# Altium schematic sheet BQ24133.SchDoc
size A4
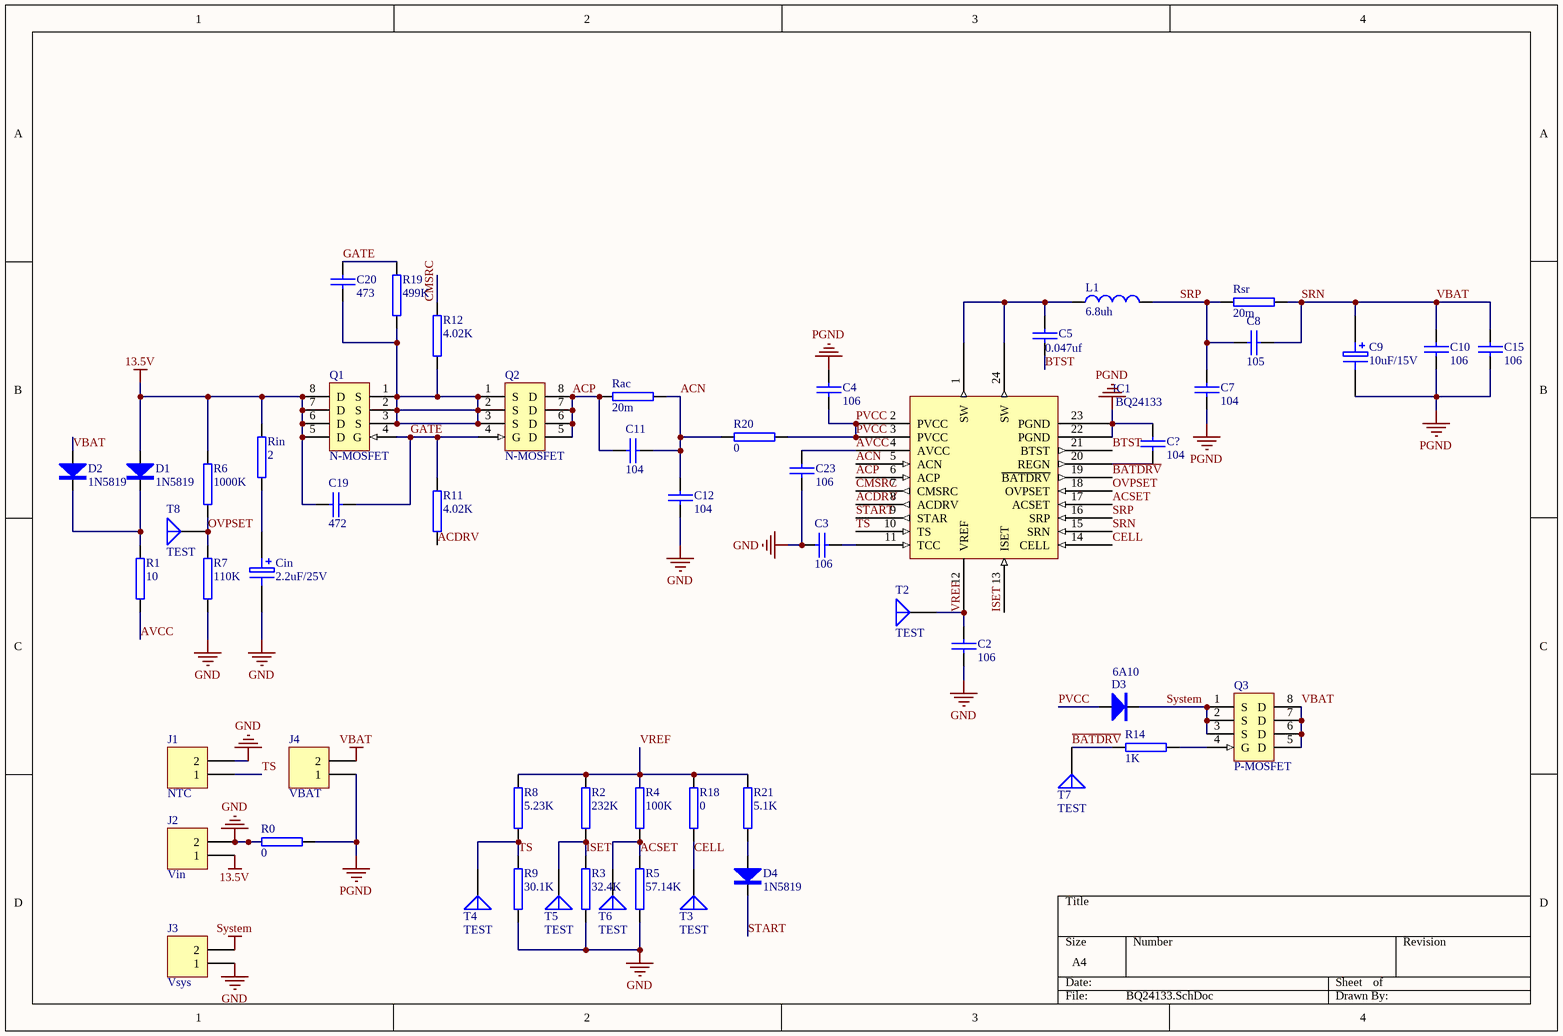
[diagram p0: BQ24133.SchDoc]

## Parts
C2  106  [C0603]
C3  106  [C0603]
C4  106  [C0603]
C5  0.047uf  [C0603]
C7  104  [C0603]
C8  105  [C0603]
C9  10uF/15V  [RB.10]
C10  106  [C1206]
C11  104  [C0603]
C12  104  [C0603]
C15  106  [C1206]
C19  472  [C0603]
C20  473  [C0603]
C23  106  [C0603]
C?  104  [C0603]
Cin  2.2uF/25V  [RB.10]
D1  1N5819  [SOD-323]
D2  1N5819  [SOD-323]
D3  6A10  [6A10]
D4  1N5819  [SOD-323]
IC1  BQ24133  [LC-VQFN-24_3.5x5.5x05P]
J1  NTC  [PH2]
J2  Vin  [VH3.96-2A]
J3  Vsys  [VH3.96-2A]
J4  VBAT  [VH3.96-2A]
L1  6.8uh  [SWPA5040S6R8]
Q1  N-MOSFET  [SOIC-8]
Q2  N-MOSFET  [SOIC-8]
Q3  P-MOSFET  [SOIC-8]
R0  0  [0805]
R1  10  [0603]
R2  232K  [0603]
R3  32.4K  [0603]
R4  100K  [0603]
R5  57.14K  [0603]
R6  1000K  [0603]
R7  110K  [0603]
R8  5.23K  [0603]
R9  30.1K  [0603]
R11  4.02K  [0603]
R12  4.02K  [0603]
R14  1K  [0603]
R18  0  [0603]
R19  499K  [0603]
R20  0  [3216[1206]]
R21  5.1K  [0603]
Rac  20m  [3225[1210]]
Rin  2  [0603]
Rsr  20m  [3225[1210]]
T2  TEST  [SIP-1]
T3  TEST  [SIP-1]
T4  TEST  [SIP-1]
T5  TEST  [SIP-1]
T6  TEST  [SIP-1]
T7  TEST  [SIP-1]
T8  TEST  [SIP-1]

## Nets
13.5V: C19.1 D1.1 J2.1 Q1.5(D) Q1.6(D) Q1.7(D) Q1.8(D) R6.1 Rin.1
GND: C2.2 C3.1 C12.2 C23.2 Cin.2 J1.2 J2.2 J3.1 R0.2 R3.1 R5.2 R7.2 R9.2
PGND: C4.1 C7.2 C9.2 C10.2 C15.1 C?.1 IC1.22(PGND) IC1.23(PGND) J4.1 R0.1
SRN: C8.2 C9.1 C10.1 C15.2 D2.1 IC1.15(SRN) J4.2 Q3.5(D) Q3.6(D) Q3.7(D) Q3.8(D) Rsr.1  [also labelled VBAT]
System: D3.2 J3.2 Q3.1(S) Q3.2(S) Q3.3(S)
ACDRV: IC1.8(ACDRV) R11.2
ACN: C11.2 C12.1 IC1.5(ACN) R20.2 Rac.1
ACP: C11.1 IC1.6(ACP) Q2.5(D) Q2.6(D) Q2.7(D) Q2.8(D) Rac.2
ACSET: IC1.17(ACSET) R4.2 R5.1 T6.1(A)
AVCC: C23.1 IC1.4(AVCC) R1.2
~{BATDRV}: IC1.19(~{BATDRV}) R14.2 T7.1(A)
BTST: C5.2 IC1.21(BTST)
CELL: IC1.14(CELL) R18.2 T3.1(A)
CMSRC: IC1.7(CMSRC) R12.1
GATE: C19.2 C20.1 Q1.4(G) Q2.4(G) R11.1 R19.1
ISET: IC1.13(ISET) R2.1 R3.2 T5.1(A)
OVPSET: IC1.18(OVPSET) R6.2 R7.1 T8.1(A)
PVCC: C4.2 D3.1 IC1.2(PVCC) IC1.3(PVCC) R20.1
SRP: C7.1 C8.1 IC1.16(SRP) L1.2 Rsr.2
START: D4.2 IC1.9(STAR)
TS: IC1.10(TS) J1.1 R8.2 R9.1 T4.1(A)
VREF: C2.1 IC1.12(VREF) R2.2 R4.1 R8.1 R18.1 R21.1 T2.1(A)
NetC3_2: C3.2 IC1.11(TCC)
NetC5_1: C5.1 IC1.1(SW) IC1.24(SW) L1.1
NetC20_2: C20.2 Q1.1(S) Q1.2(S) Q1.3(S) Q2.1(S) Q2.2(S) Q2.3(S) R12.2 R19.2
NetC?_2: C?.2 IC1.20(REGN)
NetCin_1: Cin.1 Rin.2
NetD1_2: D1.2 D2.2 R1.1
NetD4_1: D4.1 R21.2
NetQ3_4: Q3.4(G) R14.1

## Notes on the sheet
- Labels drawn without touching a wire or pin: AVCC

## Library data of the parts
C2-C5 C7 C8 C10-C12 C15 C19 C20 C23 C? = CAP: Capacitor
C9 Cin = ELECTRO1: Electrolytic Capacitor
D1-D4 = DIODE
J1-J4 = Header 2: Header, 2-Pin
L1 = Inductor: Code_IEC: 1005; Value: 10mH
Q3 = N-MOSFET
R0-R9 R11 R12 R14 R18-R21 Rac Rin Rsr = RES2
T2-T8 = TEST: Generic Antenna; Manufacturer: Generic Components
